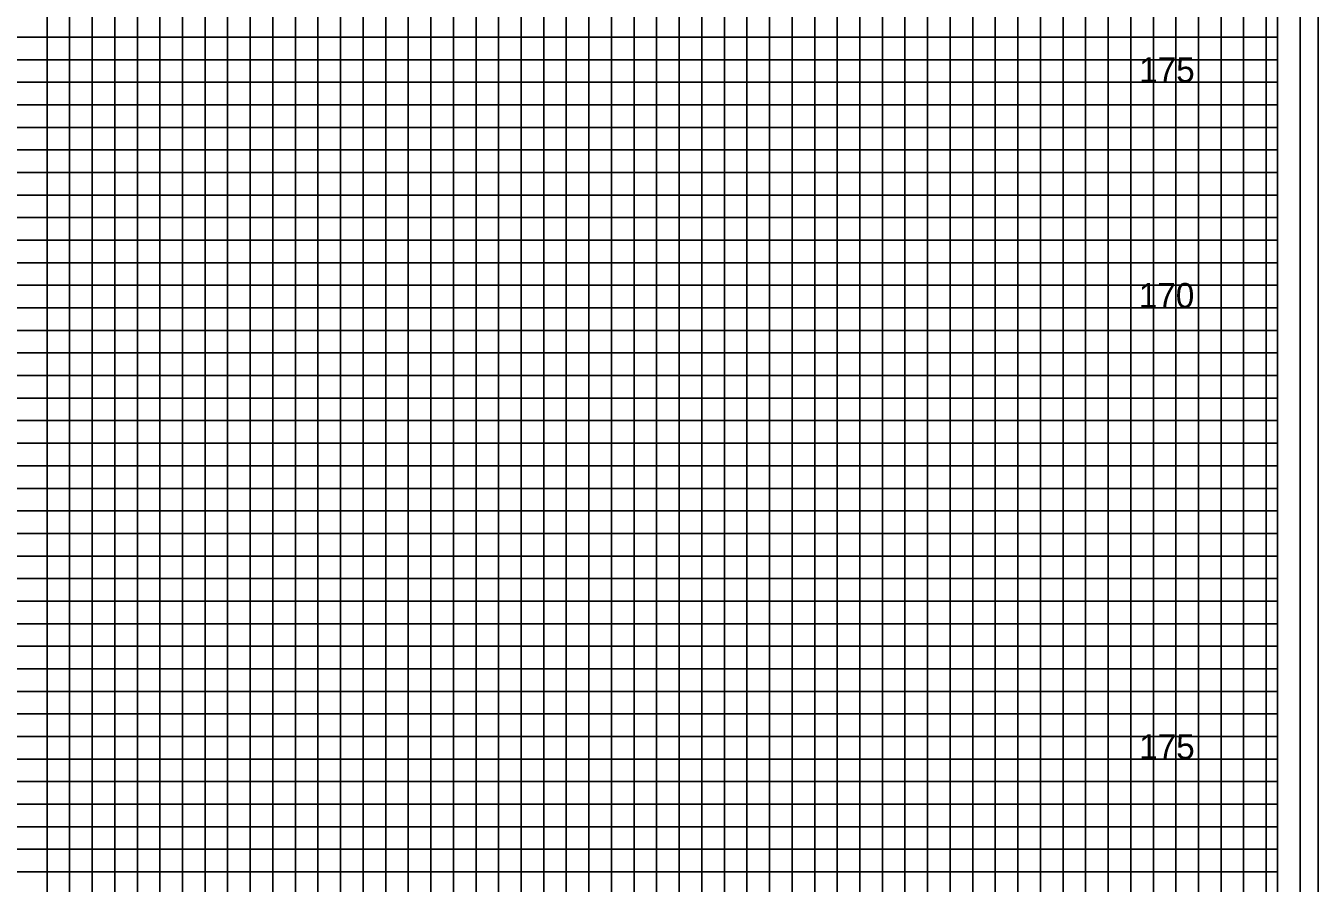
# Model space of a CAD drawing. Extents: x -4 to 103, y -2 to 67.
# Drawn here: x 74.78 to 103.4, y 32.25 to 51.25 of the extents above; entities that cross this region are included whole.
import ezdxf

# ---------------------------------------------------------------- set-up
doc = ezdxf.new("R2010")
doc.units = 0
for name, color, linetype in [('Exist XS Ground Line', 7, 'Continuous'), ('Old_Level_10', 7, 'Continuous'), ('Old_Level_5', 7, 'Continuous'), ('Old_Level_8', 7, 'Continuous'), ('Prop XS Dump Level', 7, 'Continuous'), ('Prop XS Finish Grade', 7, 'Continuous'), ('Prop XS Suitable Common Exc Shape', 7, 'Continuous')]:
    doc.layers.add(name, color=color, linetype=linetype)

msp = doc.modelspace()

# ---------------------------------------------------------------- linework, layer by layer
at = {"layer": 'Exist XS Ground Line'}
msp.add_lwpolyline([(103, 66), (-2.8, 66), (-2.8, -1), (103, -1)], close=True, dxfattribs=at)
at = {"layer": 'Old_Level_10'}
for p, q in [((91.25, 0), (91.25, 63.425)), ((93.75, 0), (93.75, 63.425)), ((96.25, 0), (96.25, 63.425)), ((98.75, 0), (98.75, 63.425)), ((101.25, 0), (101.25, 63.425)), ((76.25, 0), (76.25, 62)), ((78.75, 0), (78.75, 62)), ((81.25, 0), (81.25, 62)), ((83.75, 0), (83.75, 62)), ((86.25, 0), (86.25, 62)), ((88.75, 0), (88.75, 62)), ((0, 50), (102.5, 50)), ((0, 47.5), (102.5, 47.5)), ((0, 45), (102.5, 45)), ((0, 42.5), (102.5, 42.5)), ((0, 40), (102.5, 40)), ((0, 37.5), (102.5, 37.5)), ((0, 35), (102.5, 35)), ((0, 32.5), (102.5, 32.5))]:
    msp.add_line(p, q, dxfattribs=at)
at = {"layer": 'Old_Level_5'}
msp.add_lwpolyline([(103.4, 67.4), (-3.5, 67.4), (-3.5, -2.425), (103.4, -2.425)], close=True, dxfattribs=at)
at = {"layer": 'Old_Level_8'}
for points in [[(91.25, 0), (91.25, 63.425), (93.75, 63.425), (93.75, 0)], [(96.25, 0), (96.25, 63.425), (98.75, 63.425), (98.75, 0)], [(101.25, 0), (101.25, 63.425)], [(76.25, 0), (76.25, 62), (78.75, 62), (78.75, 0)], [(81.25, 0), (81.25, 62), (83.75, 62), (83.75, 0)], [(86.25, 0), (86.25, 62), (88.75, 62), (88.75, 0)], [(0, 47.5), (102.5, 47.5), (102.5, 50), (0, 50)], [(0, 42.5), (102.5, 42.5), (102.5, 45), (0, 45)], [(0, 37.5), (102.5, 37.5), (102.5, 40), (0, 40)], [(0, 32.5), (102.5, 32.5), (102.5, 35), (0, 35)]]:
    msp.add_lwpolyline(points, dxfattribs=at)
at = {"layer": 'Prop XS Dump Level'}
msp.add_lwpolyline([(102.5, 65), (0, 65), (0, 0), (102.5, 0)], close=True, dxfattribs=at)
at = {"layer": 'Prop XS Finish Grade'}
for points in [[(90.25, 0), (90.25, 63.425), (90.75, 63.425), (90.75, 0)], [(91.75, 0), (91.75, 63.425), (92.25, 63.425), (92.25, 0)], [(92.75, 0), (92.75, 63.425), (93.25, 63.425), (93.25, 0)], [(94.25, 0), (94.25, 63.425), (94.75, 63.425), (94.75, 0)], [(95.25, 0), (95.25, 63.425), (95.75, 63.425), (95.75, 0)], [(96.75, 0), (96.75, 63.425), (97.25, 63.425), (97.25, 0)], [(97.75, 0), (97.75, 63.425), (98.25, 63.425), (98.25, 0)], [(99.25, 0), (99.25, 63.425), (99.75, 63.425), (99.75, 0)], [(100.25, 0), (100.25, 63.425)], [(100.25, 63.425), (100.75, 63.425), (100.75, 0), (101.75, 0), (101.75, 63.425), (102.25, 63.425), (102.25, 0)], [(75.25, 0), (75.25, 62), (75.75, 62), (75.75, 0)], [(76.75, 0), (76.75, 62), (77.25, 62), (77.25, 0)], [(77.75, 0), (77.75, 62), (78.25, 62), (78.25, 0)], [(79.25, 0), (79.25, 62), (79.75, 62), (79.75, 0)], [(80.25, 0), (80.25, 62), (80.75, 62), (80.75, 0)], [(81.75, 0), (81.75, 62), (82.25, 62), (82.25, 0)], [(82.75, 0), (82.75, 62), (83.25, 62), (83.25, 0)], [(84.25, 0), (84.25, 62), (84.75, 62), (84.75, 0)], [(85.25, 0), (85.25, 62), (85.75, 62), (85.75, 0)], [(86.75, 0), (86.75, 62), (87.25, 62), (87.25, 0)], [(87.75, 0), (87.75, 62), (88.25, 62), (88.25, 0)], [(89.25, 0), (89.25, 62), (89.75, 62), (89.75, 0)], [(0, 50.5), (102.5, 50.5), (102.5, 51), (0, 51)], [(0, 49), (102.5, 49), (102.5, 49.5), (0, 49.5)], [(0, 48), (102.5, 48), (102.5, 48.5), (0, 48.5)], [(0, 46.5), (102.5, 46.5), (102.5, 47), (0, 47)], [(0, 45.5), (102.5, 45.5), (102.5, 46), (0, 46)], [(0, 44), (102.5, 44), (102.5, 44.5), (0, 44.5)], [(0, 43), (102.5, 43), (102.5, 43.5), (0, 43.5)], [(0, 41.5), (102.5, 41.5), (102.5, 42), (0, 42)], [(0, 40.5), (102.5, 40.5), (102.5, 41), (0, 41)], [(0, 39), (102.5, 39), (102.5, 39.5), (0, 39.5)], [(0, 38), (102.5, 38), (102.5, 38.5), (0, 38.5)], [(0, 36.5), (102.5, 36.5), (102.5, 37), (0, 37)], [(0, 35.5), (102.5, 35.5), (102.5, 36), (0, 36)], [(0, 34), (102.5, 34), (102.5, 34.5), (0, 34.5)], [(0, 33), (102.5, 33), (102.5, 33.5), (0, 33.5)]]:
    msp.add_lwpolyline(points, dxfattribs=at)

# ---------------------------------------------------------------- texts
at = {"layer": 'Prop XS Suitable Common Exc Shape'}
for s, p in [('175', (99.4383, 50)), ('170', (99.4296, 45)), ('175', (99.4383, 35))]:
    msp.add_text(s, height=0.55, dxfattribs=at).set_placement(p)

doc.saveas('drawing.dxf')
